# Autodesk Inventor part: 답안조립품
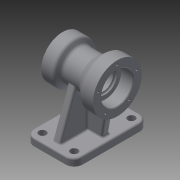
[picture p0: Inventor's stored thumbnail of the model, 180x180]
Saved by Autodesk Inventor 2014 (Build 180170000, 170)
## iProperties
Created: 2015-08
Part Number: 답안조립품
Material: Generic
Document SubType Name: Modeling
Designer: user
Density: 1 g/cm^3
Appearance: Default
Author: user
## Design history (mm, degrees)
sketch "Sketch1"
  geometry: L1 (-45, 0)-(45, 0); L2 (45, 0)-(45, 40); L3 (45, 40)-(25, 40); L4 (25, 40)-(8.315, 26); L5 (8.315, 26)-(-19.804, 26); L6 (-19.804, 26)-(-25, 35); L7 (-45, 0)-(-45, 35); L8 (-45, 35)-(-25, 35); 2 further points
  constraints: 16 end point, 3 perpendicular, 1 coincident, 1 horizontal, 1 midpoint, 1 parallel
  dimensions: "d0" = 90 distance of L1.start L1.end; "d1" = 40 distance of L1.end L2.end; "d2" = 20 distance of L2.end L3.end; "d4" = 35 distance of L1.start L7.end; "d5" = 20 distance of L7.end L6.end; "d6" = 40 deg angle of L4 L5; "d7" = 60 deg angle of L5 L6; "d8" = 52 diameter of L5 L1; "d9" = 120 deg angle of L8 L6
revolve "Revolution1" sketch "Sketch1" stored, may be unused: angle "d10" = 90 deg
sketch "Sketch2"
  geometry: C1 r 40 at (0, 0) reference; C2 r 26 at (0, 0)
  constraints: 1 centre point, 1 coincident
  dimensions: "d11" = 52 diameter of C2
extrude "Extrusion1" cut sketch "Sketch2" distance "d12" = 20; taper "d13" = 0 deg
sketch "Sketch3"
  geometry: C1 r 26 at (0, 0) reference; C2 r 19 at (0, 0)
  constraints: 1 centre point, 1 coincident
  dimensions: "d14" = 38 diameter of C2
extrude "Extrusion2" cut sketch "Sketch3" distance "d15" = 3; taper "d16" = 0 deg
sketch "Sketch4"
  geometry: C1 r 35 at (0, 0) reference; C2 r 20 at (0, 0)
  constraints: 1 centre point, 1 coincident
  dimensions: "d17" = 40 diameter of C2
extrude "Extrusion3" cut sketch "Sketch4" distance "d18" = 17; taper "d19" = 0 deg
sketch "Sketch5"
  geometry: C1 r 20 at (0, 0) reference; C2 r 16 at (0, 0)
  constraints: 1 centre point, 1 coincident
  dimensions: "d20" = 32 diameter of C2
extrude "Extrusion4" cut sketch "Sketch5" stored distance "d21" = 17; taper "d22" = 0 deg
sketch "Sketch6"
  geometry: L1 (-33, 0)-(33, 0); C1 r 40 at (0, 0) reference; A1 r 33 centre (0, 0) between (-33, 0) and (33, 0)
  constraints: 2 end point, 2 point on circle, 1 centre point, 1 coincident, 1 horizontal
  dimensions: "d23" = 66 diameter of A1; "d24" = 66 distance of L1.start L1.end
hole "Hole1" sketch "Sketch6" at (-33, 0) diameter "d25" = 3.459; stored, may be unused: countersink angle "d29" = 90 deg, drill point angle "d31" = 118 deg; dims "d26" = 10, "d27" = 4, "d28" = 2, "d30" = 13
pattern_circular "Circular Pattern1" dims angle "d33" = 360 deg
sketch "Sketch7"
  geometry: L1 (27, 0)-(-27, 0); C1 r 35 at (0, 0) reference; A1 r 27 centre (0, 0) between (27, 0) and (-27, 0)
  constraints: 2 end point, 2 point on circle, 1 centre point, 1 coincident, 1 horizontal
  dimensions: "d35" = 54 diameter of A1; "d36" = 54 distance of L1.start L1.end
hole "Hole2" sketch "Sketch7" at (27, 0) diameter "d37" = 3.459; stored, may be unused: countersink angle "d41" = 90 deg, drill point angle "d43" = 118 deg; dims "d38" = 10, "d39" = 4, "d40" = 2, "d42" = 13
pattern_circular "Circular Pattern2" dims angle "d45" = 360 deg
workplane "Work Plane2"
  workplane "Work Plane1"
sketch "Sketch8"
  geometry: L1 (-80, -35)-(-80, 35) reference; L2 (-80, 61)-(0, 61); L3 (0, 61)-(0, -61); L4 (0, -61)-(-80, -61); L5 (-80, -61)-(-80, 61); L6 (-80, 61)-(0, -61); L7 (0, 61)-(-80, -61); 3 further points
  constraints: 12 end point, 4 midpoint, 2 parallel, 1 horizontal, 1 perpendicular
  dimensions: "d48" = 80 distance of L3.end L4.end; "d49" = 122 distance of L2.end L3.end
extrude "Extrusion5" join sketch "Sketch8" distance "d50" = 12; taper "d51" = 0 deg
sketch "Sketch9"
  geometry: L1 (-66, 47)-(-14, 47); L2 (-14, 47)-(-14, -47); L3 (-14, -47)-(-66, -47); L4 (-66, -47)-(-66, 47); L5 (-66, 47)-(-14, -47); L6 (-14, 47)-(-66, -47); L7 (0, 61)-(-80, -61); C1 r 6 at (-66, -47); C2 r 6 at (-14, -47); C3 r 6 at (-66, 47); C4 r 6 at (-14, 47); 3 further points
  constraints: 14 end point, 4 centre point, 4 coincident, 4 midpoint, 2 parallel, 1 horizontal, 1 perpendicular
  dimensions: "d52" = 52 distance of L2.end L3.end; "d53" = 94 distance of L1.end L2.end; "d54" = 12 diameter of C1; "d55" = 12 diameter of C2; "d56" = 12 diameter of C3; "d57" = 12 diameter of C4
extrude "Extrusion6" cut sketch "Sketch9" stored distance "d58" = 12; taper "d59" = 0 deg
workplane "Work Plane4"
  workplane "Work Plane3"
sketch "Sketch10"
  geometry: L1 (0, 0)-(122, 0) reference; L2 (0, 0)-(10, 0); L3 (122, 0)-(112, 0); L4 (112, 0)-(86.091, 71.185); L5 (10, 0)-(35.909, 71.185); C1 r 26 at (61, 78) reference; A1 r 26 centre (61, 78) between (86.091, 71.185) and (35.909, 71.185) reference; 1 further point
  constraints: 8 end point, 2 point on circle, 2 point on line
  dimensions: "d61" = 10 distance of L1.start L2.end; "d62" = 10 distance of L1.end L3.end; "d63" = 70 deg angle of L4 L1; "d64" = 70 deg angle of L5 L1
extrude "Extrusion7" join sketch "Sketch10" stored distance "d65" = 12; taper "d66" = 0 deg
workplane "Work Plane5"
sketch "Sketch11"
  geometry: L1 (0, 12)-(80, 12) reference; L2 (80, 12)-(70, 12); L3 (80, 55)-(60, 55) reference; L4 (0, 12)-(10, 12); L5 (10, 50)-(-10, 50) reference; L6 (10, 12)-(70, 12); L7 (10, 55)-(25.054, 64.918); L8 (25.054, 64.918)-(55.716, 64.918); L9 (55.716, 64.918)-(61.325, 57.401); L10 (61.325, 57.401)-(70, 55); L11 (10, 12)-(2.767, 53.019); L12 (70, 12)-(70, 57.693); L13 (70, 57.693)-(60.476, 57.693); L14 (60.476, 57.693)-(55.716, 64.918); L15 (25.054, 64.918)-(10, 55); L16 (10, 55)-(2.767, 53.019); 1 further point
  constraints: 26 end point, 4 perpendicular, 2 point on line, 1 collinear, 1 midpoint, 1 parallel
  dimensions: "d67" = 10 distance of L1.end L2.end; "d68" = 10 distance of L1.start L4.end; "d71" = 80 deg angle of L1 L11
extrude "Extrusion8" join sketch "Sketch11" stored distance "d72" = 12; taper "d73" = 0 deg
fillet "Fillet1" dims "d74" = 14
fillet "Fillet2" dims "d75" = 3
chamfer "Chamfer1" distance "d76" = 1; stored, may be unused: second distance "d77" = 2, angle "d78" = 45 deg
fillet "Fillet3" dims "d79" = 5
fillet "Fillet4" dims "d80" = 5
fillet "Fillet5" dims "d81" = 5
fillet "Fillet6" dims "d82" = 5
fillet "Fillet7" dims "d83" = 0.3
fillet "Fillet8" dims "d84" = 0.3
fillet "Fillet9" dims "d85" = 3
fillet "Fillet10" dims "d86" = 3
fillet "Fillet11" dims "d87" = 3
fillet "Fillet12" dims "d88" = 3
fillet "Fillet13" dims "d89" = 3
fillet "Fillet14" dims "d90" = 3
fillet "Fillet15" dims "d91" = 3
fillet "Fillet16" dims "d92" = 3
fillet "Fillet17" dims "d93" = 3
fillet "Fillet18" dims "d94" = 3
fillet "Fillet19" dims "d95" = 3
workplane "Work Plane6"
sketch "Sketch12"
  geometry: L1 (-21, 37.119)-(-21, 0) reference; L2 (-28, -3)-(-17, -3) reference; L3 (-17, -3)-(-17, 21); L4 (-21, 21)-(-5, 21); 2 further points
  constraints: 4 end point, 2 perpendicular, 1 coincident, 1 point on line, 1 other
  dimensions: "d96" = 24 distance of L2.end L3.end; "d97" = 16 distance of L4.start L4.end; "d98" = 24 distance between parallel lines of L2 L4
emboss "Emboss1" sketch "Sketch12" dims "d99" = 0.5, "d100" = 0
body "Solid1"
node "Projected Loop1"
